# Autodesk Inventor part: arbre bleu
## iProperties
Author: Chris...
Created: 2002-01
Part Number: arbre bleu
Material: Par défaut
Document SubType Name: Modélisation
Designer: Chris...
Control State: 0
Master: False
Checked Out: False
PropertySet Name: Design Tracking Control
Shininess: 20.0
PropertySet Name: _Private Model Information
Length Units: 11269
Angle Units: 11283
Time Units: 11279
Mass Units: 11290
Length Display Precision: 3
Angle Display Precision: 2
Compacted: False
Density: 0.0
Volumn: 0.0
Area: 0.0
PropertySet Name: Model Information
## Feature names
1. Balayage1
